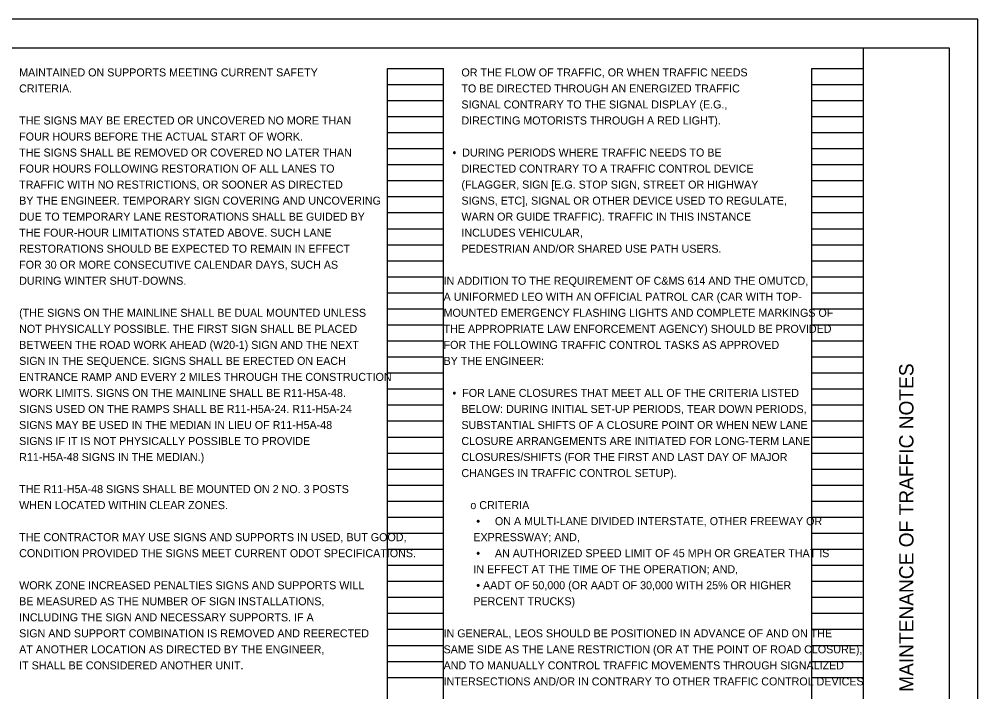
# Model space of a CAD drawing. Extents: x 0 to 34, y 0 to 22.
# Drawn here: x 17.24 to 34, y 10.25 to 22 of the extents above; entities that cross this region are included whole.
import ezdxf

# ---------------------------------------------------------------- set-up
doc = ezdxf.new("R2010")
doc.units = 0
for name, color, linetype in [('SH_Border', 7, 'Continuous'), ('SH_Cut_Line', 7, 'Continuous'), ('SH_Data', 7, 'Continuous'), ('SH_Text', 7, 'Continuous')]:
    doc.layers.add(name, color=color, linetype=linetype)

msp = doc.modelspace()

# ---------------------------------------------------------------- linework, layer by layer
at = {"layer": 'SH_Border'}
msp.add_line((32, 0.5), (32, 21.5), dxfattribs=at)
msp.add_lwpolyline([(1.5, 21.5), (33.5, 21.5), (33.5, 0.5), (1.5, 0.5)], close=True, dxfattribs=at)
at = {"layer": 'SH_Cut_Line'}
msp.add_lwpolyline([(0, 0), (34, 0), (34, 22), (0, 22)], close=True, dxfattribs=at)
at = {"layer": 'SH_Data'}
for p, q in [((23.68, 0.98), (23.68, 21.14)), ((23.68, 21.14), (24.66, 21.14)), ((24.66, 0.98), (24.66, 21.14)), ((31.1, 0.98), (31.1, 21.14)), ((31.1, 21.14), (32, 21.14)), ((32, 0.98), (32, 21.14)), ((23.68, 20.86), (24.66, 20.86)), ((31.1, 20.86), (32, 20.86)), ((23.68, 20.58), (24.66, 20.58)), ((31.1, 20.58), (32, 20.58)), ((23.68, 20.3), (24.66, 20.3)), ((31.1, 20.3), (32, 20.3)), ((23.68, 20.02), (24.66, 20.02)), ((31.1, 20.02), (32, 20.02)), ((23.68, 19.74), (24.66, 19.74)), ((31.1, 19.74), (32, 19.74)), ((23.68, 19.46), (24.66, 19.46)), ((31.1, 19.46), (32, 19.46)), ((23.68, 19.18), (24.66, 19.18)), ((31.1, 19.18), (32, 19.18)), ((23.68, 18.9), (24.66, 18.9)), ((31.1, 18.9), (32, 18.9)), ((23.68, 18.62), (24.66, 18.62)), ((31.1, 18.62), (32, 18.62)), ((23.68, 18.34), (24.66, 18.34)), ((31.1, 18.34), (32, 18.34)), ((23.68, 18.06), (24.66, 18.06)), ((31.1, 18.06), (32, 18.06)), ((23.68, 17.78), (24.66, 17.78)), ((31.1, 17.78), (32, 17.78)), ((23.68, 17.5), (24.66, 17.5)), ((31.1, 17.5), (32, 17.5)), ((23.68, 17.22), (24.66, 17.22)), ((31.1, 17.22), (32, 17.22)), ((23.68, 16.94), (24.66, 16.94)), ((31.1, 16.94), (32, 16.94)), ((23.68, 16.66), (24.66, 16.66)), ((31.1, 16.66), (32, 16.66)), ((23.68, 16.38), (24.66, 16.38)), ((31.1, 16.38), (32, 16.38)), ((23.68, 16.1), (24.66, 16.1)), ((31.1, 16.1), (32, 16.1)), ((23.68, 15.82), (24.66, 15.82)), ((31.1, 15.82), (32, 15.82)), ((23.68, 15.54), (24.66, 15.54)), ((31.1, 15.54), (32, 15.54)), ((23.68, 15.26), (24.66, 15.26)), ((31.1, 15.26), (32, 15.26)), ((23.68, 14.98), (24.66, 14.98)), ((31.1, 14.98), (32, 14.98)), ((23.68, 14.7), (24.66, 14.7)), ((31.1, 14.7), (32, 14.7)), ((23.68, 14.42), (24.66, 14.42)), ((31.1, 14.42), (32, 14.42)), ((23.68, 14.14), (24.66, 14.14)), ((31.1, 14.14), (32, 14.14)), ((23.68, 13.86), (24.66, 13.86)), ((31.1, 13.86), (32, 13.86)), ((23.68, 13.58), (24.66, 13.58)), ((31.1, 13.58), (32, 13.58)), ((23.68, 13.3), (24.66, 13.3)), ((31.1, 13.3), (32, 13.3)), ((23.68, 13.02), (24.66, 13.02)), ((31.1, 13.02), (32, 13.02)), ((23.68, 12.74), (24.66, 12.74)), ((31.1, 12.74), (32, 12.74)), ((23.68, 12.46), (24.66, 12.46)), ((31.1, 12.46), (32, 12.46)), ((23.68, 12.18), (24.66, 12.18)), ((31.1, 12.18), (32, 12.18)), ((23.68, 11.9), (24.66, 11.9)), ((31.1, 11.9), (32, 11.9)), ((23.68, 11.62), (24.66, 11.62)), ((31.1, 11.62), (32, 11.62)), ((23.68, 11.34), (24.66, 11.34)), ((31.1, 11.34), (32, 11.34)), ((23.68, 11.06), (24.66, 11.06)), ((31.1, 11.06), (32, 11.06)), ((23.68, 10.78), (24.66, 10.78)), ((31.1, 10.78), (32, 10.78)), ((23.68, 10.5), (24.66, 10.5)), ((31.1, 10.5), (32, 10.5))]:
    msp.add_line(p, q, dxfattribs=at)

# ---------------------------------------------------------------- texts
msp.add_text('MAINTENANCE OF TRAFFIC NOTES', height=0.25, rotation=90, dxfattribs=at).set_placement((32.875, 10.247))
at = {"layer": 'SH_Text'}
for s, p in [('MAINTAINED ON SUPPORTS MEETING CURRENT SAFETY', (17.24, 21)), ('      OR THE FLOW OF TRAFFIC, OR WHEN TRAFFIC NEEDS', (24.66, 21)), ('CRITERIA.', (17.24, 20.72)), ('      TO BE DIRECTED THROUGH AN ENERGIZED TRAFFIC', (24.66, 20.72)), ('      SIGNAL CONTRARY TO THE SIGNAL DISPLAY (E.G.,', (24.66, 20.44)), ('THE SIGNS MAY BE ERECTED OR UNCOVERED NO MORE THAN', (17.24, 20.16)), ('      DIRECTING MOTORISTS THROUGH A RED LIGHT).', (24.66, 20.16)), ('FOUR HOURS BEFORE THE ACTUAL START OF WORK.', (17.24, 19.88)), ('THE SIGNS SHALL BE REMOVED OR COVERED NO LATER THAN', (17.24, 19.6)), ('   •  DURING PERIODS WHERE TRAFFIC NEEDS TO BE', (24.66, 19.6)), ('FOUR HOURS FOLLOWING RESTORATION OF ALL LANES TO', (17.24, 19.32)), ('      DIRECTED CONTRARY TO A TRAFFIC CONTROL DEVICE', (24.66, 19.32)), ('TRAFFIC WITH NO RESTRICTIONS, OR SOONER AS DIRECTED', (17.24, 19.04)), ('      (FLAGGER, SIGN [E.G. STOP SIGN, STREET OR HIGHWAY', (24.66, 19.04)), ('BY THE ENGINEER. TEMPORARY SIGN COVERING AND UNCOVERING', (17.24, 18.76)), ('      SIGNS, ETC], SIGNAL OR OTHER DEVICE USED TO REGULATE,', (24.66, 18.76)), ('DUE TO TEMPORARY LANE RESTORATIONS SHALL BE GUIDED BY', (17.24, 18.48)), ('      WARN OR GUIDE TRAFFIC). TRAFFIC IN THIS INSTANCE', (24.66, 18.48)), ('THE FOUR-HOUR LIMITATIONS STATED ABOVE. SUCH LANE', (17.24, 18.2)), ('      INCLUDES VEHICULAR,', (24.66, 18.2)), ('RESTORATIONS SHOULD BE EXPECTED TO REMAIN IN EFFECT', (17.24, 17.92)), ('      PEDESTRIAN AND/OR SHARED USE PATH USERS.', (24.66, 17.92)), ('FOR 30 OR MORE CONSECUTIVE CALENDAR DAYS, SUCH AS', (17.24, 17.64)), ('DURING WINTER SHUT-DOWNS.', (17.24, 17.36)), ('IN ADDITION TO THE REQUIREMENT OF C&MS 614 AND THE OMUTCD,', (24.66, 17.36)), ('A UNIFORMED LEO WITH AN OFFICIAL PATROL CAR (CAR WITH TOP-', (24.66, 17.08)), ('(THE SIGNS ON THE MAINLINE SHALL BE DUAL MOUNTED UNLESS', (17.24, 16.8)), ('MOUNTED EMERGENCY FLASHING LIGHTS AND COMPLETE MARKINGS OF', (24.66, 16.8)), ('NOT PHYSICALLY POSSIBLE. THE FIRST SIGN SHALL BE PLACED', (17.24, 16.52)), ('THE APPROPRIATE LAW ENFORCEMENT AGENCY) SHOULD BE PROVIDED', (24.66, 16.52)), ('BETWEEN THE ROAD WORK AHEAD (W20-1) SIGN AND THE NEXT', (17.24, 16.24)), ('FOR THE FOLLOWING TRAFFIC CONTROL TASKS AS APPROVED', (24.66, 16.24)), ('SIGN IN THE SEQUENCE. SIGNS SHALL BE ERECTED ON EACH', (17.24, 15.96)), ('BY THE ENGINEER:', (24.66, 15.96)), ('ENTRANCE RAMP AND EVERY 2 MILES THROUGH THE CONSTRUCTION', (17.24, 15.68)), ('WORK LIMITS. SIGNS ON THE MAINLINE SHALL BE R11-H5A-48.', (17.24, 15.4)), ('   •  FOR LANE CLOSURES THAT MEET ALL OF THE CRITERIA LISTED', (24.66, 15.4)), ('SIGNS USED ON THE RAMPS SHALL BE R11-H5A-24. R11-H5A-24', (17.24, 15.12)), ('      BELOW: DURING INITIAL SET-UP PERIODS, TEAR DOWN PERIODS,', (24.66, 15.12)), ('SIGNS MAY BE USED IN THE MEDIAN IN LIEU OF R11-H5A-48', (17.24, 14.84)), ('      SUBSTANTIAL SHIFTS OF A CLOSURE POINT OR WHEN NEW LANE', (24.66, 14.84)), ('SIGNS IF IT IS NOT PHYSICALLY POSSIBLE TO PROVIDE', (17.24, 14.56)), ('      CLOSURE ARRANGEMENTS ARE INITIATED FOR LONG-TERM LANE', (24.66, 14.56)), ('R11-H5A-48 SIGNS IN THE MEDIAN.)', (17.24, 14.28)), ('      CLOSURES/SHIFTS (FOR THE FIRST AND LAST DAY OF MAJOR', (24.66, 14.28)), ('      CHANGES IN TRAFFIC CONTROL SETUP).', (24.66, 14)), ('THE R11-H5A-48 SIGNS SHALL BE MOUNTED ON 2 NO. 3 POSTS', (17.24, 13.72)), ('WHEN LOCATED WITHIN CLEAR ZONES.', (17.24, 13.44)), ('         o CRITERIA', (24.66, 13.44)), ('           •     ON A MULTI-LANE DIVIDED INTERSTATE, OTHER FREEWAY OR', (24.66, 13.16)), ('THE CONTRACTOR MAY USE SIGNS AND SUPPORTS IN USED, BUT GOOD,', (17.24, 12.88)), ('          EXPRESSWAY; AND,', (24.66, 12.88)), ('CONDITION PROVIDED THE SIGNS MEET CURRENT ODOT SPECIFICATIONS.', (17.24, 12.6)), ('           •     AN AUTHORIZED SPEED LIMIT OF 45 MPH OR GREATER THAT IS', (24.66, 12.6)), ('          IN EFFECT AT THE TIME OF THE OPERATION; AND,', (24.66, 12.32)), ('WORK ZONE INCREASED PENALTIES SIGNS AND SUPPORTS WILL', (17.24, 12.04)), ('           • AADT OF 50,000 (OR AADT OF 30,000 WITH 25% OR HIGHER', (24.66, 12.04)), ('BE MEASURED AS THE NUMBER OF SIGN INSTALLATIONS,', (17.24, 11.76)), ('          PERCENT TRUCKS)', (24.66, 11.76)), ('INCLUDING THE SIGN AND NECESSARY SUPPORTS. IF A', (17.24, 11.48)), ('SIGN AND SUPPORT COMBINATION IS REMOVED AND REERECTED', (17.24, 11.2)), ('IN GENERAL, LEOS SHOULD BE POSITIONED IN ADVANCE OF AND ON THE', (24.66, 11.2)), ('AT ANOTHER LOCATION AS DIRECTED BY THE ENGINEER,', (17.24, 10.92)), ('SAME SIDE AS THE LANE RESTRICTION (OR AT THE POINT OF ROAD CLOSURE),', (24.66, 10.92)), ('IT SHALL BE CONSIDERED ANOTHER UNIT.', (17.24, 10.64)), ('AND TO MANUALLY CONTROL TRAFFIC MOVEMENTS THROUGH SIGNALIZED', (24.66, 10.64)), ('INTERSECTIONS AND/OR IN CONTRARY TO OTHER TRAFFIC CONTROL DEVICES', (24.66, 10.36))]:
    msp.add_text(s, height=0.14, dxfattribs=at).set_placement(p)

doc.saveas('drawing.dxf')
